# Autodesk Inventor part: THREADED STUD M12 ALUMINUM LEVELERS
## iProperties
Created: 2007-03
Part Number: THREADED STUD M12 ALUMINUM LEVELERS
Document SubType Name: Modeling
Designer: Andy Moles
Material: Steel
Mass: 62.4986 g
Surface Area: 33.7932 cm^2
Volume: 7.9616 cm^3
Density: 7.85 g/cm^3
Author: Andy Moles
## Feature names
1. Revolution1
2. Extrusion1
3. Extrusion2
4. Chamfer1
